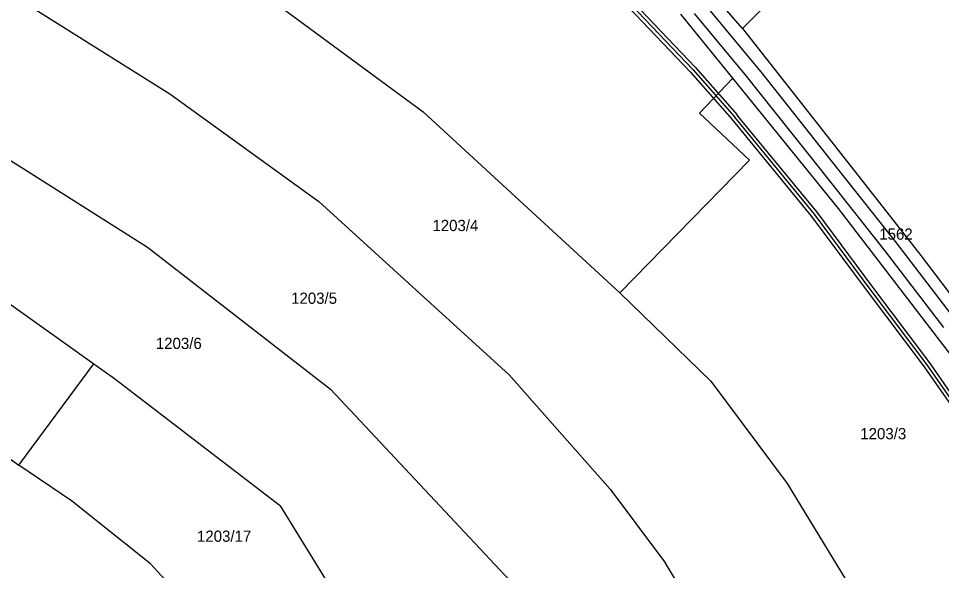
# Model space of a CAD drawing. Extents: x -510185 to -506993, y -1126306 to -1123642.
# Drawn here: x -509663.2 to -509243.9, y -1126078.2 to -1125827.4 of the extents above; entities that cross this region are included whole.
import ezdxf

# ---------------------------------------------------------------- set-up
doc = ezdxf.new("R2010")
doc.units = 0
for name, color, linetype in [('parcelni hranice', 7, 'Continuous'), ('telefonica', 7, 'Continuous'), ('u_Telefonica', 7, 'Continuous'), ('ˇ2', 7, 'Continuous'), ('ˇ4', 7, 'Continuous')]:
    doc.layers.add(name, color=color, linetype=linetype)

msp = doc.modelspace()

# ---------------------------------------------------------------- linework, layer by layer
at = {"layer": 'parcelni hranice'}
for p, q in [((-509334.32, -1125831.88), (-509270.54, -1125768.18)), ((-509577.61, -1125797.39), (-509479.33, -1125869.79)), ((-509334.32, -1125831.88), (-509359.24, -1125803.31)), ((-509662.24, -1125818.93), (-509594.45, -1125861.54)), ((-509338.67, -1125854.56), (-509362.36, -1125825.34)), ((-509334.32, -1125831.88), (-509302.48, -1125872.44)), ((-509338.67, -1125854.56), (-509353.9, -1125870.45)), ((-509290.67, -1125913.76), (-509338.67, -1125854.56)), ((-509594.45, -1125861.54), (-509526.69, -1125910.59)), ((-509479.33, -1125869.79), (-509390.07, -1125951.98)), ((-509353.9, -1125870.45), (-509331.18, -1125891.68)), ((-509302.48, -1125872.44), (-509253.29, -1125935.06)), ((-509680.09, -1125883.44), (-509604.57, -1125931.25)), ((-509331.18, -1125891.68), (-509390.07, -1125951.98)), ((-509526.69, -1125910.59), (-509440.34, -1125989.27)), ((-509219.69, -1126006.46), (-509290.67, -1125913.76)), ((-509604.57, -1125931.25), (-509521.38, -1125995.87)), ((-509253.29, -1125935.06), (-509220.87, -1125978.05)), ((-509669.68, -1125955.29), (-509628.88, -1125984.28)), ((-509390.07, -1125951.98), (-509348.7, -1125992.21)), ((-509663.04, -1126030.29), (-509628.88, -1125984.28)), ((-509628.88, -1125984.28), (-509619.53, -1125990.92)), ((-509440.34, -1125989.27), (-509394.46, -1126041.2)), ((-509714.94, -1125993.06), (-509663.04, -1126030.29)), ((-509619.53, -1125990.92), (-509544.19, -1126048.77)), ((-509348.7, -1125992.21), (-509314.05, -1126038.6)), ((-509521.38, -1125995.87), (-509437.89, -1126085.06)), ((-509639.1, -1126046.54), (-509663.04, -1126030.29)), ((-509314.05, -1126038.6), (-509285.32, -1126085.9)), ((-509394.46, -1126041.2), (-509369.3, -1126074.88)), ((-509603.23, -1126075.15), (-509639.1, -1126046.54)), ((-509486.92, -1126141.74), (-509544.19, -1126048.77)), ((-509550.1, -1126132.91), (-509603.23, -1126075.15)), ((-509328.41, -1126142.49), (-509369.3, -1126074.88))]:
    msp.add_line(p, q, dxfattribs=at)
at = {"layer": 'telefonica'}
for points in [[(-509415.19, -1125787.88), (-509383.88, -1125820.11), (-509355.82, -1125849.52), (-509336.74, -1125871.21)], [(-509417.35, -1125789.97), (-509386.05, -1125822.19), (-509358.03, -1125851.55), (-509338.99, -1125873.2)], [(-509188.65, -1126074.91), (-509202.69, -1126054.24), (-509225.62, -1126017.86), (-509249.3, -1125983.88), (-509275.16, -1125949.5), (-509300.47, -1125915.43), (-509336.7, -1125871.25)], [(-509191.13, -1126076.6), (-509205.2, -1126055.89), (-509228.12, -1126019.51), (-509251.73, -1125985.64), (-509277.57, -1125951.3), (-509302.83, -1125917.28), (-509339.02, -1125873.16)]]:
    msp.add_lwpolyline(points, dxfattribs=at)
at = {"layer": 'u_Telefonica'}
for points in [[(-509416.27, -1125788.92), (-509384.97, -1125821.15), (-509356.92, -1125850.54), (-509337.86, -1125872.21)], [(-509416.27, -1125788.92), (-509384.97, -1125821.15), (-509356.92, -1125850.54), (-509337.86, -1125872.21)], [(-509189.89, -1126075.76), (-509203.95, -1126055.06), (-509226.87, -1126018.69), (-509250.52, -1125984.76), (-509276.37, -1125950.4), (-509301.65, -1125916.36), (-509337.86, -1125872.21)], [(-509189.89, -1126075.76), (-509203.95, -1126055.06), (-509226.87, -1126018.69), (-509250.52, -1125984.76), (-509276.37, -1125950.4), (-509301.65, -1125916.36), (-509337.86, -1125872.21)]]:
    msp.add_lwpolyline(points, dxfattribs=at)
at = {"layer": 'ˇ4'}
for p, q in [((-509325.32, -1125852.39), (-509351.35, -1125821)), ((-509333.18, -1125852.89), (-509356.18, -1125825.15)), ((-509298.72, -1125895.95), (-509333.18, -1125852.89)), ((-509293.88, -1125892.01), (-509325.32, -1125852.39)), ((-509264.86, -1125928.78), (-509293.88, -1125892.01)), ((-509269.67, -1125932.73), (-509298.72, -1125895.95)), ((-509237.56, -1125964.26), (-509264.86, -1125928.78)), ((-509242.83, -1125967.72), (-509269.67, -1125932.73))]:
    msp.add_line(p, q, dxfattribs=at)

# ---------------------------------------------------------------- texts
at = {"layer": 'ˇ2'}
for s, p in [('1203/4', (-509475.15, -1125923.97)), ('1562', (-509272.22, -1125927.89)), ('1203/5', (-509539.33, -1125957.03)), ('1203/6', (-509600.77, -1125977.55)), ('1203/3', (-509280.83, -1126018.58)), ('1203/17', (-509582.07, -1126065.16))]:
    msp.add_text(s, height=5.1, dxfattribs=at).set_placement(p)

doc.saveas('drawing.dxf')
